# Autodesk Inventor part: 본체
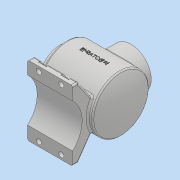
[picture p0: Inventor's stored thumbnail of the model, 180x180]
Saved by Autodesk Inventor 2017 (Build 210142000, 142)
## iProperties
Part Number: 본체
Material: 일반
Document SubType Name: Modeling
Designer: MRC
Density: 1 g/cm^3
Appearance: 기본값
Author: MRC
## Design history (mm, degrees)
sketch "스케치7"
  geometry: L1 (0, 0)-(120, 0); L2 (0, 0)-(0, 36); L3 (0, 36)-(12, 36); L4 (12, 36)-(12, 50); L5 (12, 50)-(108.336, 50); A1 r 113 centre (7, 0) between (120, 0) and (108.336, 50)
  constraints: 10 end point, 2 horizontal, 2 perpendicular, 2 point on circle, 1 centre point, 1 point on line, 1 vertical
  dimensions: "d11" = 120 distance of L1.start L1.end; "d12" = 72 diameter of L3 L1; "d13" = 100 diameter of L5 L1; "d14" = 113 radius of A1; "d15" = 12 distance of L2.end L3.end
revolve "회전1" sketch "스케치7" stored, may be unused: angle "d16" = 90 deg
sketch "스케치8"
  geometry: L1 (0, 0)-(0, 27); L2 (0, -36)-(0, 36) reference; L3 (0, 27)-(19, 27); L4 (19, 27)-(19, 43); L5 (19, 43)-(104.499, 43); L6 (0, 0)-(120, 0); A1 r 113 centre (0, 0) between (113, 0) and (104.499, 43); A2 r 113 centre (7, 0) between (108.336, -50) and (108.336, 50) reference
  constraints: 10 end point, 3 point on circle, 3 point on line, 2 horizontal, 2 perpendicular, 1 centre point
  dimensions: "d17" = 54 diameter of L3 L6; "d18" = 86 diameter of L5 L6; "d19" = 19 distance of L1.end L3.end; "d20" = 113 radius of A1; "d102" = 7 distance of A2.centre A1.centre
revolve "회전2" sketch "스케치8" stored, may be unused: angle "d22" = 90 deg
node "작업 평면1"
sketch "스케치9"
  geometry: C1 r 36 at (-62, 0); 1 further point
  constraints: 1 centre point, 1 horizontal alignment
  dimensions: "d24" = 72 diameter of C1; "d25" = 62 distance of point (0, 0) C1.centre
extrude "돌출2" join sketch "스케치9" stored distance "d26" = 12; taper "d27" = 0 deg
sketch "스케치10"
  geometry: C1 r 36 at (0, 0) reference; C2 r 27 at (0, 0); 1 further point
  constraints: 1 centre point, 1 coincident
  dimensions: "d28" = 54 diameter of C2
extrude "돌출3" cut sketch "스케치10" distance "d29" = 47.75; taper "d30" = 0 deg
sketch "스케치11"
  geometry: C1 r 27 at (0, 0) reference; 2 further points
  constraints: 1 vertical alignment
  dimensions: "d31" = 32.5 distance of point (0, 32.5) C1.centre
hole "구멍1" sketch "스케치11" at (0, 32.5) diameter "d32" = 3.242; stored, may be unused: countersink angle "d36" = 90 deg, drill point angle "d38" = 118 deg; dims "d33" = 8, "d34" = 4, "d35" = 2, "d37" = 10
node "작업 평면2"
sketch "스케치12"
  geometry: L1 (-42.278, -26.694)-(-67, -62); L2 (-67, -62)-(-77, -62); L3 (-77, -62)-(-77, 62); L4 (-77, 62)-(-67, 62); L5 (-67, 62)-(-42.278, 26.694); A1 r 50 centre (0, 0) between (-42.278, -26.694) and (-42.278, 26.694) reference; 1 further point
  constraints: 10 end point, 2 perpendicular, 2 point on circle, 1 horizontal
  dimensions: "d43" = 10 distance of L3.end L4.end; "d44" = 77 distance from line of L3 point (0, 0); "d45" = 10 distance of L1.end L2.end; "d46" = 55 deg angle of L4 L5; "d47" = 55 deg angle of L2 L1; "d48" = 124 distance of L2.end L3.end; "d49" = 62 vertical distance of L2.end point (0, 0)
extrude "돌출4" join sketch "스케치12" stored distance "d50" = 80; taper "d51" = 0 deg
sketch "스케치13"
  geometry: L1 (62, -77)-(-62, -77) reference; A1 r 52.096 centre (0, -112.096) between (38.5, -77) and (-38.5, -77); 1 further point
  constraints: 2 point on circle, 2 point on line, 1 centre point, 1 vertical alignment
  dimensions: "d52" = 17 distance edge to line of A1 L1; "d53" = 77 distance of A1.start A1.end
extrude "돌출5" cut sketch "스케치13" distance "d54" = 80; taper "d55" = 0 deg
sketch "스케치14"
  geometry: 2 further points
  constraints: 1 vertical alignment
  dimensions: "d56" = 32.5 distance of point (0, 32.5) point (0, 0)
hole "구멍2" sketch "스케치14" at (0, 32.5) diameter "d57" = 3.242; stored, may be unused: countersink angle "d61" = 90 deg, drill point angle "d63" = 118 deg; dims "d58" = 8, "d59" = 4, "d60" = 2, "d62" = 10
sketch "스케치15"
  geometry: L1 (80, 23.5)-(80, 0) reference; L2 (0, 0)-(80, 0) reference; C1 r 4.5 at (60, 8); 1 further point
  constraints: 1 centre point
  dimensions: "d67" = 9 diameter of C1; "d68" = 20 distance from line of C1.centre L1; "d69" = 8 distance from line of C1.centre L2
extrude "돌출6" cut sketch "스케치15" distance "d70" = 6; taper "d71" = 0 deg
sketch "스케치16"
  geometry: L1 (7, -8)-(7, 0); L2 (-7, 0)-(-7, -8); L3 (-7, -8)-(7, -8); L4 (-60, -8)-(20, -8) reference; C1 r 4.5 at (0, 0) reference; A1 r 7 centre (0, 0) between (7, 0) and (-7, 0); 1 further point
  constraints: 6 end point, 2 point on circle, 2 tangent, 1 centre point, 1 coincident, 1 perpendicular, 1 point on line, 1 vertical
  dimensions: "d89" = 14 distance of L2.end L1.start; "d90" = 7 radius of A1
extrude "돌출7" cut sketch "스케치16" distance "d73" = 27.5; taper "d74" = 0 deg
chamfer "모따기1" distance "d81" = 1; stored, may be unused: second distance "d82" = 2, angle "d83" = 45 deg
chamfer "모따기2" distance "d84" = 1; stored, may be unused: second distance "d85" = 2, angle "d86" = 45 deg
fillet "모깎기1" dims "d87" = 3
fillet "모깎기2" dims "d88" = 3
fillet "모깎기3" dims "d94" = 3
fillet "모깎기4" dims "d95" = 3
fillet "모깎기5" dims "d96" = 3
node "작업 평면3"
sketch "스케치17"
  geometry: L1 (0, -36)-(0, 36) reference; 3 further points
  constraints: 1 horizontal alignment, 1 midpoint, 1 other
  dimensions: "d98" = 62 distance from line of point (62, 0) L1
feature "엠보싱1" sketch "스케치17" dims "d11" = 120, "d12" = 72, "d13" = 100, "d14" = 113, "d15" = 12, "d99" = 0.5, "d100" = 0
fillet "모깎기6" dims "d103" = 3
node "솔리드2"
pattern_circular "원형 패턴1" dims angle "d40" = 360 deg
pattern_circular "원형 패턴2" dims angle "d65" = 360 deg
pattern_linear "직사각형 패턴2" dims "d93" = 40
mirror "미러1"
node "투영된 루프1"
node "투영된 루프2"
other parameters: "d23" = 65, "d97" = 101
